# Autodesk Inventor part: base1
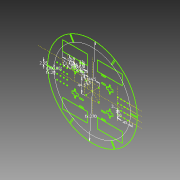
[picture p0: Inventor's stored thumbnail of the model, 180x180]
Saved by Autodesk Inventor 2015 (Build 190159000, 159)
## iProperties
Created: 2017-04
Part Number: base1
Material: Generic
Document SubType Name: Modeling
Designer: mcalderon
Density: 1 g/cm^3
Appearance: Default
Author: mcalderon
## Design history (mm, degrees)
sketch "Sketch1" dims "d32" = 3.8
  geometry: L1 (114.987, 1.943)-(134.986, 1.943); L2 (134.996, -1.007)-(114.996, -1.007); L3 (114.996, -1.007)-(114.987, 1.943); L4 (55.811, 100.553)-(65.811, 117.873); L5 (68.371, 116.406)-(58.371, 99.086); L6 (58.371, 99.086)-(55.811, 100.553); L7 (-59.176, 98.61)-(-69.175, 115.93); L8 (-66.626, 117.414)-(-56.626, 100.093); L9 (-56.626, 100.093)-(-59.176, 98.61); L10 (-114.987, -1.943)-(-134.986, -1.943); L11 (-134.996, 1.007)-(-114.996, 1.007); L12 (-114.996, 1.007)-(-114.987, -1.943); L13 (-55.811, -100.553)-(-65.811, -117.873); L14 (-68.371, -116.406)-(-58.371, -99.086); L15 (-58.371, -99.086)-(-55.811, -100.553); L16 (59.176, -98.61)-(69.175, -115.93); L17 (66.626, -117.414)-(56.626, -100.093); L18 (56.626, -100.093)-(59.176, -98.61); L19 (95, 0)-(-95, 0); L20 (0, 90)-(0, -60); L21 (15, 60)-(15, 90); L22 (90, 60)-(90, 90); L23 (90, 60)-(15, 60); L24 (90, 90)-(15, 90); L25 (-90, 60)-(-90, 90); L26 (-90, 60)-(-15, 60); L27 (-90, 90)-(-15, 90); L28 (-15, 60)-(-15, 90); L29 (90, -60)-(15, -60); L30 (90, -60)-(90, -90); L31 (90, -90)-(15, -90); L32 (15, -60)-(15, -90); L33 (-15, -60)-(-15, -90); L34 (-90, -90)-(-15, -90); L35 (-90, -60)-(-15, -60); L36 (-90, -60)-(-90, -90); L37 (52.5, 60)-(52.5, 0); L38 (15, 60)-(15, 0); L39 (73.861, 60)-(73.861, 38); L40 (90, 38)-(165, 38); L41 (89.159, 38)-(89.159, 25); L42 (89.159, 25)-(15, 25); L43 (73.861, 38)-(73.861, 25); L44 (49.25, 25)-(55.75, 25); L45 (55.75, 38)-(49.25, 38); L46 (62, 28.25)-(62, 34.75); L47 (43, 34.75)-(43, 28.25); L48 (43, 34.75)-(38.6, 34.75); L49 (38.6, 34.75)-(38.6, 38); L50 (38.6, 38)-(27.6, 38); L51 (27.6, 38)-(27.6, 34.75); L52 (27.6, 34.75)-(38.6, 34.75); L53 (38.6, 38)-(38.6, 55.5); L54 (38.6, 55.5)-(27.6, 55.5); L55 (27.6, 55.5)-(27.6, 58.5); L56 (27.6, 58.5)-(38.6, 58.5); L57 (38.6, 58.5)-(38.6, 55.5); L58 (55.75, 25)-(55.75, 28.25); L59 (55.75, 34.75)-(55.75, 38); L60 (43, 28.25)-(49.25, 28.25); L61 (55.75, 28.25)-(62, 28.25); L62 (62, 34.75)-(55.75, 34.75); L63 (49.25, 34.75)-(43, 34.75); L64 (49.25, 38)-(49.25, 34.75)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; C1 r 1.9 at (52.5, -41.9); C2 r 1.9 at (52.5, -21.1); C3 r 1.9 at (-52.5, -41.9); C4 r 1.9 at (-52.5, -21.1); C5 r 1.9 at (-52.5, 21.1); C6 r 1.9 at (-52.5, 41.9); C7 r 1.5 at (18.75, 18.75); C8 r 1.5 at (18.75, -18.75); C9 r 1.5 at (-18.75, -18.75); C10 r 1.5 at (-18.75, 18.75); C11 r 1.5 at (-76.155, -22.25); C12 r 1.5 at (-76.155, -7.25); C13 r 1.5 at (-76.155, 7.75); C14 r 1.5 at (-76.155, 22.75); C15 r 1.5 at (-86.155, -22.25); C16 r 1.5 at (-86.155, -7.25); C17 r 1.5 at (-86.155, 7.75); C18 r 1.5 at (-86.155, 22.75); C19 r 1.5 at (-96.155, -22.25); C20 r 1.5 at (-96.155, -7.25); C21 r 1.5 at (-96.155, 7.75); C22 r 1.5 at (-96.155, 22.75); C23 r 1.5 at (-106.155, -22.25); C24 r 1.5 at (-106.155, -7.25); C25 r 1.5 at (-106.155, 7.75); C26 r 1.5 at (-106.155, 22.75); C27 r 1.5 at (106.155, -22.25); C28 r 1.5 at (106.155, -7.25); C29 r 1.5 at (106.155, 7.75); C30 r 1.5 at (106.155, 22.75); C31 r 1.5 at (96.155, 22.75); C32 r 1.5 at (96.155, 7.75); C33 r 1.5 at (96.155, -7.25); C34 r 1.5 at (96.155, -22.25); C35 r 1.5 at (86.155, -22.25); C36 r 1.5 at (86.155, -7.25); C37 r 1.5 at (86.155, 7.75); C38 r 1.5 at (86.155, 22.75); C39 r 1.5 at (76.155, 22.75); C40 r 1.5 at (76.155, 7.75); C41 r 1.5 at (76.155, -7.25); C42 r 1.5 at (76.155, -22.25); A1 r 135 centre (0, 0) between (135, 0) and (134.986, 1.943); 6 further points
  constraints: 302 end point, 101 symmetric about line, 43 centre point, 14 parallel, 11 horizontal, 11 perpendicular, 10 point on line, 9 vertical, 5 midpoint, 3 point on circle, 2 collinear, 2 vertical alignment, 131 other
  dimensions: "d1" = 270 diameter of A1 (computed from space); "d2" = 20 distance of L2.start L2.end (= 0.5 x space); "d3" = 2.95 distance of L1.end L2.start; "d6" = 360 deg dimension on point (0, 0) L1.start (derived); "d17" = 75 distance between parallel lines of L21 L22; "d19" = 22 distance of L39.start L39.end; "d21" = 13 distance of L41.start L41.end; "d22" = 6.5 distance of L45.end L45.start; "d23" = 19 distance of L47.start L46.end; "d24" = 6.5 distance of L46.end L46.start; "d25" = 4.4 distance of L47.start L48.end; "d26" = 11 distance of L49.end L50.end; "d27" = 3.25 distance of L50.end L51.end; "d28" = 17.5 distance of L49.end L53.end; "d29" = 11 distance of L53.end L54.end; "d30" = 3 distance of L54.end L55.end; "d31" = 11 distance of L55.end L56.end; "d33" = 2 distance between parallel lines of L66 L45; "d34" = 44.5 distance of L131.end L130.end; "d35" = 44.5 distance of L130.end L129.end; "d36" = 3 diameter of C7; "d37" = 3.5 distance from line of L131 C7.centre; "d38" = 3 diameter of C11; "d39" = 45 distance of L136.start L136.end; "d42" = 15 distance of L136.start L137.start; "d45" = 10 distance of L136.start L140.start
